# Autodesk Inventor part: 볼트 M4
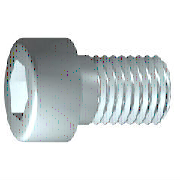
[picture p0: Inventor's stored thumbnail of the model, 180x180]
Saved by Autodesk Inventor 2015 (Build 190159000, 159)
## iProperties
IsCustomPart: 0
Created: 2012-02
Part Number: 볼트 M4
Material: 스테인리스강
Description: 6각 소켓 머리 캡 나사
Document SubType Name: Modeling
Standard: ISO 4762
Designer: mduedu
Standard Revision: Fourth edition 2004-03-01
Standards Organization: ISO
Language: ko-KR
Size Designation: M4 x 10
Categories: <MemberInstance><Categories><Category DisplayName="조임쇠" InternalName="e4da775c-781d-43d5-af7c-5136215cf5a6" Mnemonic="FSTN"><Category DisplayName="볼트" InternalN
Density: 7.75 g/cm^3
Appearance: 반광택
Author: mduedu
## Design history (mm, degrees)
sketch "스케치1"
  geometry: L1 (-1, 0)-(10, 0); L2 (10, 0)-(10, 2); L3 (10, 2)-(1.75, 2); L4 (1.75, 2)-(1.32, 2); L5 (1.32, 2)-(0, 2); L6 (0, 2)-(0, 3.5); L7 (0, 3.5)-(-4, 3.5); L8 (-4, 3.5)-(-4, 1.732); L9 (-4, 1.732)-(-2, 1.732); L10 (-2, 1.732)-(-1, 0); L11 (-6.8, 0)-(12.8, 0) reference; L12 (0, -0.7)-(0, 4.2) reference; L13 (1.75, 2)-(0, 2)
  constraints: 22 end point, 6 parallel, 2 collinear, 2 perpendicular, 1 horizontal, 1 point on line
  dimensions: "d1" = 8.25 distance from line of L3.end L2 (= GEL); "d2" = 0.42952 distance of L4.end L3.end (computed from GAL); "d3" = 4 distance between parallel lines of L8 L6 (= KOH); "d4" = 2 distance of L8.end L9.end (= INTI); "d5" = 60 deg angle of L10 L1; "d6" = 4 diameter of L3 L1 (= GD); "d7" = 4 diameter of L5 L1 (= BDM); "d8" = 3.4641 diameter of L9 L1 (= 1.1547 x SW); "d9" = 7 diameter of L7 L1 (= KOD); "d26" = 10 distance between parallel lines of L12 L2 (= NLG)
revolve "본체" sketch "스케치1" stored, may be unused: angle "d10" = 90 deg
sketch "스케치2"
  geometry: L1 (0, -4.9)-(0, 4.9) reference; L2 (-4.9, 0)-(4.9, 0) reference; L3 (1.732, 0)-(0.866, -1.5); L4 (0.866, -1.5)-(-0.866, -1.5); L5 (-0.866, -1.5)-(-1.732, 0); L6 (-1.732, 0)-(-0.866, 1.5); L7 (-0.866, 1.5)-(0.866, 1.5); L8 (0.866, 1.5)-(1.732, 0); 2 further points
  constraints: 12 end point, 1 coincident, 1 horizontal alignment, 1 point on line, 12 other
extrude "슬롯" join sketch "스케치2" stored distance "d11" = 10; taper "d12" = 0 deg
workplane "Work Plane1"
fillet "Fillet2" dims "d30" = 0.1 (= R)
body "Solid1"
fillet "모깎기1" dims "d17" = 0.4 (= RR)
feature "스레드" dims "d13" = 8.25 (= GEL), "d14" = 0
chamfer "모따기1" distance "d15" = 0.42941 (= -0.5 x SPD + 0.5 x GD); stored, may be unused: second distance "d16" = 0.42941 (= GUL), angle "d27" = 45 deg
other parameters: "GD" = 4 [user parameter; used in 2 equation terms], "NLG" = 10 [user parameter; used in 1 equation term], "GEL" = 8.25 [user parameter; used in 2 equation terms], "KOD" = 7 [user parameter; used in 1 equation term], "KOH" = 4 [user parameter; used in 1 equation term], "INTI" = 2 [user parameter; used in 1 equation term], "GAL" = 0.42941 (= 0.61345 x PTC) [user parameter; used in 1 equation term], "GUL" = 0.42941 (= 0.61345 x PTC) [user parameter; used in 1 equation term], "BDM" = 4 (= NND) [user parameter; used in 1 equation term], "SW" = 3 [user parameter; used in 2 equation terms], "RR" = 0.4 [user parameter; used in 1 equation term], "SPD" = 3.14117 (= NND - 1.2269 x PTC) [user parameter; used in 1 equation term], "d19" = 0, "d28" = 0, "d29" = 0, "R" = 0.1 [user parameter; used in 1 equation term], "TOA" = 30 deg [user parameter], "GD1" = 3.14117 (= THREADDIA - 1.2269 x PTC) [user parameter], "THREADDIA" = 4 [user parameter; used in 1 equation term], "FAWI" = 45 deg [user parameter], "TPU" = 14.28571 (computed from PTC) [user parameter], "PTC" = 0.7 [user parameter; used in 5 equation terms], "NND" = 4 [user parameter; used in 2 equation terms], "E0" = 3.465 (= 1.155 x SW) [user parameter]
